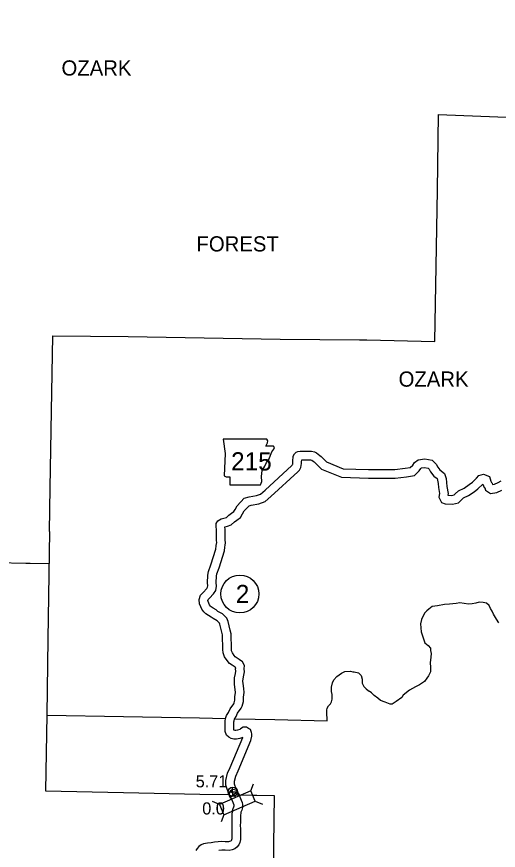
# Model space of a CAD drawing. Extents: x -939622 to -934245, y 1383184 to 1385301.
# Drawn here: x -936291.7 to -936241.4, y 1384683.1 to 1384770.1 of the extents above; entities that cross this region are included whole.
import ezdxf

# ---------------------------------------------------------------- set-up
doc = ezdxf.new("R2010")
doc.units = 0
for name, color, linetype in [('Level 10', 7, 'Continuous'), ('Level 11', 7, 'Continuous'), ('Level 2', 7, 'Continuous'), ('Level 20', 7, 'Continuous'), ('Level 21', 7, 'Continuous'), ('Level 25', 7, 'Continuous'), ('Level 26', 7, 'Continuous'), ('Level 27', 7, 'Continuous'), ('Level 8', 7, 'Continuous')]:
    doc.layers.add(name, color=color, linetype=linetype)

msp = doc.modelspace()

# ---------------------------------------------------------------- linework, layer by layer
at = {"layer": 'Level 10'}
for points in [[(-936270.814, 1384716.503), (-936270.849, 1384716.935), (-936270.833, 1384717.202), (-936270.672, 1384717.473), (-936270.337, 1384717.707), (-936269.901, 1384717.788), (-936269.76, 1384717.84), (-936269.519, 1384718.06), (-936269.233, 1384718.284), (-936268.989, 1384718.458), (-936268.88, 1384718.651), (-936268.648, 1384719.064), (-936267.91, 1384719.851), (-936267.396, 1384720.004), (-936266.628, 1384720.119), (-936266.219, 1384720.278), (-936265.738, 1384720.688), (-936262.945, 1384723.262), (-936262.904, 1384723.3), (-936262.873, 1384723.367), (-936262.86, 1384723.412), (-936262.85, 1384723.536), (-936262.835, 1384723.69), (-936262.813, 1384724.23), (-936262.691, 1384724.481), (-936262.506, 1384724.634), (-936262.342, 1384724.703), (-936262.094, 1384724.758), (-936260.892, 1384724.753), (-936260.598, 1384724.68), (-936260.398, 1384724.582), (-936260.198, 1384724.443), (-936260.043, 1384724.316), (-936259.906, 1384724.188), (-936259.344, 1384723.643), (-936257.591, 1384722.921), (-936254.949, 1384722.845)], [(-936269.917, 1384716.577), (-936269.94, 1384716.865), (-936269.66, 1384716.917), (-936269.283, 1384717.057), (-936268.937, 1384717.373), (-936268.695, 1384717.563), (-936268.304, 1384717.841), (-936268.096, 1384718.21), (-936267.917, 1384718.528), (-936267.42, 1384719.058), (-936267.2, 1384719.123), (-936266.396, 1384719.244), (-936265.751, 1384719.494), (-936265.141, 1384720.015), (-936262.331, 1384722.603), (-936262.159, 1384722.765), (-936262.027, 1384723.054), (-936261.97, 1384723.251), (-936261.954, 1384723.456), (-936261.937, 1384723.627), (-936261.928, 1384723.857), (-936261.004, 1384723.853), (-936260.907, 1384723.829), (-936260.855, 1384723.803), (-936260.741, 1384723.724), (-936260.636, 1384723.638), (-936260.526, 1384723.536), (-936259.846, 1384722.877), (-936257.781, 1384722.026), (-936254.974, 1384721.945)], [(-936254.957, 1384722.845), (-936252.885, 1384722.826), (-936252.221, 1384722.838), (-936251.132, 1384722.963), (-936250.598, 1384723.052), (-936250.34, 1384723.305), (-936250.151, 1384723.564), (-936249.771, 1384723.862), (-936249.099, 1384723.943), (-936248.304, 1384723.814), (-936247.899, 1384723.387), (-936247.743, 1384723.085), (-936247.51, 1384722.792), (-936247.033, 1384722.434), (-936246.87, 1384721.918), (-936246.812, 1384721.484), (-936246.773, 1384721.071), (-936246.654, 1384720.348), (-936246.682, 1384720.145), (-936246.279, 1384720.132), (-936246.022, 1384720.185), (-936245.92, 1384720.296), (-936245.563, 1384720.621), (-936244.993, 1384720.907), (-936244.467, 1384721.259), (-936244.126, 1384721.515), (-936243.684, 1384721.935), (-936243.447, 1384722.203), (-936242.948, 1384722.356), (-936242.334, 1384722.096), (-936242.196, 1384721.611), (-936242.138, 1384721.489), (-936242.062, 1384721.407), (-936242.014, 1384721.28), (-936241.826, 1384721.309), (-936241.44, 1384721.491), (-936241.133, 1384721.65)], [(-936254.966, 1384721.945), (-936252.881, 1384721.926), (-936252.161, 1384721.939), (-936251.007, 1384722.072), (-936250.171, 1384722.211), (-936249.657, 1384722.714), (-936249.498, 1384722.933), (-936249.414, 1384722.999), (-936249.117, 1384723.034), (-936248.748, 1384722.974), (-936248.64, 1384722.86), (-936248.502, 1384722.594), (-936248.142, 1384722.142), (-936247.805, 1384721.888), (-936247.752, 1384721.722), (-936247.707, 1384721.382), (-936247.666, 1384720.955), (-936247.564, 1384720.336), (-936247.615, 1384719.965), (-936247.348, 1384719.394), (-936246.958, 1384719.254), (-936246.202, 1384719.229), (-936245.556, 1384719.363), (-936245.285, 1384719.657), (-936245.048, 1384719.872), (-936244.539, 1384720.128), (-936243.946, 1384720.524), (-936243.544, 1384720.827), (-936243.045, 1384721.3), (-936242.891, 1384720.978), (-936242.84, 1384720.922), (-936242.742, 1384720.667), (-936242.235, 1384720.336), (-936241.561, 1384720.439), (-936241.063, 1384720.674)], [(-936269.34, 1384688.638), (-936269.563, 1384689.151), (-936269.712, 1384689.481), (-936269.825, 1384689.888), (-936269.84, 1384690.406), (-936269.664, 1384691.148), (-936269.383, 1384691.753), (-936268.077, 1384694.871), (-936268.377, 1384694.787), (-936268.716, 1384694.699), (-936269.012, 1384694.721), (-936269.268, 1384694.782), (-936269.529, 1384694.913), (-936269.755, 1384695.129), (-936269.9, 1384695.501), (-936269.912, 1384695.79), (-936269.895, 1384695.933), (-936269.902, 1384696.167), (-936269.9, 1384696.346), (-936269.901, 1384696.585), (-936269.861, 1384696.845), (-936269.753, 1384697.165), (-936269.574, 1384697.483), (-936269.393, 1384697.868), (-936269.022, 1384698.391), (-936268.97, 1384698.496), (-936268.884, 1384698.757), (-936268.894, 1384699.109), (-936268.847, 1384699.581), (-936268.867, 1384699.893), (-936268.927, 1384700.412), (-936268.952, 1384700.745), (-936268.943, 1384701.115), (-936268.836, 1384701.543), (-936268.809, 1384701.782), (-936268.816, 1384702.038), (-936268.81, 1384702.162), (-936268.98, 1384702.282), (-936269.165, 1384702.423), (-936269.474, 1384702.609), (-936269.713, 1384702.906), (-936269.964, 1384703.304), (-936270.128, 1384703.726), (-936270.154, 1384704.051), (-936270.187, 1384705.573), (-936270.253, 1384705.879), (-936270.453, 1384706.709), (-936270.499, 1384706.823), (-936270.731, 1384707.051), (-936271.161, 1384707.281), (-936271.376, 1384707.449), (-936271.648, 1384707.623), (-936271.914, 1384707.796), (-936272.126, 1384707.993), (-936272.331, 1384708.281), (-936272.435, 1384708.523), (-936272.583, 1384708.839), (-936272.615, 1384709.259), (-936272.478, 1384709.714), (-936272.215, 1384710.018), (-936271.837, 1384710.416), (-936271.743, 1384710.56), (-936271.714, 1384710.715), (-936271.746, 1384711.032), (-936271.702, 1384711.814), (-936271.646, 1384712.187), (-936271.39, 1384712.881), (-936270.883, 1384714.516), (-936270.851, 1384714.885), (-936270.802, 1384715.103), (-936270.788, 1384715.204), (-936270.809, 1384715.463), (-936270.815, 1384716.537)], [(-936268.515, 1384688.997), (-936268.74, 1384689.515), (-936268.864, 1384689.789), (-936268.929, 1384690.022), (-936268.937, 1384690.313), (-936268.809, 1384690.851), (-936268.559, 1384691.39), (-936267.236, 1384694.548), (-936267.141, 1384695.008), (-936267.117, 1384695.264), (-936267.158, 1384695.409), (-936267.257, 1384695.708), (-936267.466, 1384695.83), (-936267.674, 1384695.956), (-936268.015, 1384695.954), (-936268.307, 1384695.787), (-936268.384, 1384695.719), (-936268.611, 1384695.656), (-936268.798, 1384695.608), (-936268.874, 1384695.613), (-936268.958, 1384695.633), (-936268.992, 1384695.65), (-936269.007, 1384695.689), (-936269.01, 1384695.754), (-936268.993, 1384695.892), (-936269.001, 1384696.175), (-936269, 1384696.344), (-936269.001, 1384696.518), (-936268.983, 1384696.631), (-936268.927, 1384696.798), (-936268.774, 1384697.07), (-936268.613, 1384697.413), (-936268.248, 1384697.927), (-936268.135, 1384698.153), (-936267.98, 1384698.626), (-936267.993, 1384699.077), (-936267.944, 1384699.565), (-936267.97, 1384699.973), (-936268.031, 1384700.497), (-936268.051, 1384700.769), (-936268.046, 1384700.993), (-936267.949, 1384701.382), (-936267.908, 1384701.744), (-936267.916, 1384702.027), (-936267.896, 1384702.382), (-936268.108, 1384702.769), (-936268.448, 1384703.008), (-936268.659, 1384703.169), (-936268.873, 1384703.297), (-936268.978, 1384703.429), (-936269.156, 1384703.711), (-936269.241, 1384703.929), (-936269.255, 1384704.096), (-936269.289, 1384705.68), (-936269.376, 1384706.08), (-936269.594, 1384706.987), (-936269.736, 1384707.334), (-936270.191, 1384707.783), (-936270.668, 1384708.038), (-936270.856, 1384708.185), (-936271.16, 1384708.379), (-936271.357, 1384708.508), (-936271.446, 1384708.59), (-936271.543, 1384708.726), (-936271.614, 1384708.891), (-936271.698, 1384709.071), (-936271.705, 1384709.16), (-936271.671, 1384709.271), (-936271.548, 1384709.413), (-936271.129, 1384709.855), (-936270.892, 1384710.217), (-936270.805, 1384710.675), (-936270.843, 1384711.053), (-936270.806, 1384711.722), (-936270.77, 1384711.962), (-936270.538, 1384712.592), (-936269.995, 1384714.341), (-936269.96, 1384714.747), (-936269.916, 1384714.943), (-936269.884, 1384715.178), (-936269.909, 1384715.501), (-936269.915, 1384716.543)], [(-936268.68, 1384689.342), (-936268.519, 1384689.006), (-936268.462, 1384688.879)]]:
    msp.add_lwpolyline(points, dxfattribs=at)
at = {"layer": 'Level 11'}
for points in [[(-936268.68, 1384689.342), (-936268.519, 1384689.006), (-936268.37, 1384688.671), (-936268.225, 1384688.339), (-936268.144, 1384688.107), (-936268.095, 1384687.87), (-936268.1, 1384687.581), (-936268.178, 1384687.297), (-936268.266, 1384687.099), (-936268.289, 1384687.034), (-936268.306, 1384686.741), (-936268.315, 1384686.386), (-936268.321, 1384686.058), (-936268.327, 1384685.712), (-936268.321, 1384685.364), (-936268.318, 1384684.998), (-936268.312, 1384684.632), (-936268.319, 1384684.248), (-936268.365, 1384683.933), (-936268.487, 1384683.665), (-936268.682, 1384683.438), (-936268.916, 1384683.266), (-936269.189, 1384683.15), (-936269.505, 1384683.097), (-936269.918, 1384683.107), (-936270.254, 1384683.118), (-936270.562, 1384683.094)], [(-936269.491, 1384688.954), (-936269.336, 1384688.629), (-936269.193, 1384688.309), (-936269.064, 1384688.01), (-936269.013, 1384687.866), (-936268.997, 1384687.786), (-936268.998, 1384687.709), (-936269.028, 1384687.601), (-936269.101, 1384687.436), (-936269.18, 1384687.217), (-936269.205, 1384686.778), (-936269.215, 1384686.406), (-936269.221, 1384686.074), (-936269.227, 1384685.712), (-936269.221, 1384685.352), (-936269.218, 1384684.986), (-936269.212, 1384684.632), (-936269.218, 1384684.32), (-936269.237, 1384684.19), (-936269.253, 1384684.155), (-936269.298, 1384684.103), (-936269.365, 1384684.053), (-936269.443, 1384684.02), (-936269.569, 1384683.999), (-936269.892, 1384684.006), (-936270.274, 1384684.019), (-936270.653, 1384683.989), (-936271.024, 1384683.943), (-936271.356, 1384683.902), (-936271.742, 1384683.864), (-936272.185, 1384683.776), (-936272.418, 1384683.666), (-936272.649, 1384683.509), (-936272.829, 1384683.303), (-936272.969, 1384683.075)]]:
    msp.add_lwpolyline(points, dxfattribs=at)
at = {"layer": 'Level 2'}
for points in [[(-936255.136, 1384736.381), (-936248.036, 1384736.189), (-936247.889, 1384744.061), (-936247.757, 1384751.98), (-936247.652, 1384759.881), (-936239.705, 1384759.57), (-936239.604, 1384767.528), (-936239.509, 1384775.26), (-936231.735, 1384775.112), (-936223.865, 1384774.959), (-936216.107, 1384774.837), (-936215.972, 1384782.762), (-936207.838, 1384782.718), (-936207.773, 1384785.45)], [(-936255.136, 1384736.381), (-936248.036, 1384736.189), (-936247.889, 1384744.061), (-936247.757, 1384751.98), (-936247.652, 1384759.881), (-936239.705, 1384759.57), (-936239.604, 1384767.528), (-936239.509, 1384775.26), (-936231.735, 1384775.112), (-936223.865, 1384774.959), (-936216.107, 1384774.837), (-936215.972, 1384782.762), (-936207.838, 1384782.718), (-936207.773, 1384785.45)], [(-936288.235, 1384716.364), (-936288.172, 1384720.935), (-936288.036, 1384728.922), (-936287.89, 1384736.781), (-936280.017, 1384736.702), (-936272.099, 1384736.564), (-936264.189, 1384736.432), (-936255.904, 1384736.382), (-936255.136, 1384736.381)], [(-936288.235, 1384716.364), (-936288.172, 1384720.935), (-936288.036, 1384728.922), (-936287.89, 1384736.781), (-936280.017, 1384736.702), (-936272.099, 1384736.564), (-936264.189, 1384736.432), (-936255.904, 1384736.382), (-936255.136, 1384736.381)], [(-936288.235, 1384716.364), (-936288.398, 1384705.128), (-936288.512, 1384697.23), (-936288.653, 1384689.325), (-936280.508, 1384689.147), (-936272.567, 1384688.98), (-936269.576, 1384688.92)], [(-936288.235, 1384716.364), (-936288.398, 1384705.128), (-936288.512, 1384697.23), (-936288.653, 1384689.325), (-936280.508, 1384689.147), (-936272.567, 1384688.98), (-936269.537, 1384688.92)], [(-936268.413, 1384688.897), (-936264.806, 1384688.825), (-936264.912, 1384680.993)], [(-936266.971, 1384688.869), (-936264.806, 1384688.825), (-936264.912, 1384680.993)]]:
    msp.add_lwpolyline(points, dxfattribs=at)
at = {"layer": 'Level 20'}
for p, q in [((-936267.239, 1384689.32), (-936266.947, 1384690.056)), ((-936270.508, 1384687.902), (-936271.245, 1384688.193)), ((-936266.766, 1384688.23), (-936266.029, 1384687.939)), ((-936270.036, 1384686.812), (-936270.327, 1384686.076))]:
    msp.add_line(p, q, dxfattribs=at)
msp.add_lwpolyline([(-936270.036, 1384686.812), (-936266.766, 1384688.23), (-936267.239, 1384689.32), (-936270.508, 1384687.902)], close=True, dxfattribs=at)
at = {"layer": 'Level 21'}
msp.add_lwpolyline([(-936270.132, 1384726.022), (-936269.904, 1384724.499), (-936270.006, 1384722.19), (-936269.803, 1384722.063), (-936269.422, 1384722.063), (-936269.422, 1384721.251), (-936266.224, 1384721.251), (-936266.072, 1384721.581), (-936266.123, 1384722.114), (-936266.047, 1384722.723), (-936265.768, 1384723.205), (-936265.59, 1384723.56), (-936265.336, 1384723.941), (-936265.184, 1384724.347), (-936265.057, 1384724.677), (-936264.829, 1384724.956), (-936264.778, 1384725.134), (-936264.879, 1384725.261), (-936265.666, 1384725.261), (-936265.489, 1384725.616), (-936265.463, 1384725.844), (-936265.568, 1384726.02)], close=True, dxfattribs=at)
at = {"layer": 'Level 26'}
for p, q in [((-936269.607, 1384689.198), (-936268.631, 1384689.22)), ((-936269.389, 1384688.637), (-936268.636, 1384689.259)), ((-936268.782, 1384688.668), (-936269.324, 1384689.324)), ((-936269.108, 1384688.721), (-936269.13, 1384689.697))]:
    msp.add_line(p, q, dxfattribs=at)
msp.add_circle((-936269.119, 1384689.209), 0.488, dxfattribs=at)
msp.add_arc((-936269.013, 1384688.948), 0.488, 340.26675, 242.44563, dxfattribs=at)
at = {"layer": 'Level 27'}
msp.add_circle((-936268.376, 1384709.851), 1.98, dxfattribs=at)
at = {"layer": 'Level 8'}
for points in [[(-936310.654, 1384713.404), (-936304.177, 1384713.293), (-936296.207, 1384713.175), (-936288.283, 1384713.03)], [(-936290.692, 1384713.074), (-936288.283, 1384713.03)], [(-936241.364, 1384706.843), (-936241.605, 1384707.208), (-936241.934, 1384707.741), (-936242.051, 1384708.054), (-936242.225, 1384708.33), (-936242.376, 1384708.657), (-936242.65, 1384708.879), (-936242.981, 1384708.956), (-936243.405, 1384709.013), (-936243.749, 1384708.877), (-936244.146, 1384708.829), (-936244.544, 1384708.806), (-936245.433, 1384708.916), (-936245.831, 1384708.866), (-936246.503, 1384708.779), (-936247.044, 1384708.738), (-936247.751, 1384708.617), (-936248.304, 1384708.539), (-936248.682, 1384708.279), (-936248.881, 1384708.101), (-936249.116, 1384707.858), (-936249.443, 1384707.194), (-936249.523, 1384706.732), (-936249.476, 1384705.907), (-936249.341, 1384705.487), (-936249.086, 1384704.741), (-936248.736, 1384704.478), (-936248.505, 1384704.198), (-936248.497, 1384703.952), (-936248.428, 1384703.635), (-936248.452, 1384703.244), (-936248.542, 1384702.674), (-936248.497, 1384702.216), (-936248.504, 1384701.723), (-936248.684, 1384701.323), (-936248.865, 1384701.072), (-936249.109, 1384700.737), (-936249.626, 1384700.371), (-936250.064, 1384700.152), (-936250.671, 1384699.805), (-936251.355, 1384699.31), (-936251.467, 1384699.065), (-936252.075, 1384698.625), (-936252.5, 1384698.349), (-936252.707, 1384698.371), (-936253.209, 1384698.556), (-936253.719, 1384698.743), (-936253.984, 1384698.975), (-936254.38, 1384699.276), (-936254.64, 1384699.543), (-936254.874, 1384699.695)], [(-936268.836, 1384696.839), (-936264.734, 1384696.743), (-936259.284, 1384696.634), (-936259.285, 1384696.781), (-936259.275, 1384696.964), (-936259.297, 1384697.222), (-936259.302, 1384697.483), (-936259.294, 1384697.747), (-936259.283, 1384697.921), (-936259.123, 1384698.174), (-936258.933, 1384698.391), (-936258.818, 1384698.59), (-936258.742, 1384698.879), (-936258.754, 1384699.358), (-936258.822, 1384699.661), (-936258.819, 1384700.143), (-936258.726, 1384700.597), (-936258.587, 1384700.889), (-936258.257, 1384701.248), (-936257.768, 1384701.588), (-936257.416, 1384701.749), (-936256.833, 1384701.811), (-936256.599, 1384701.738)], [(-936256.599, 1384701.738), (-936256.459, 1384701.712), (-936256.015, 1384701.613), (-936255.732, 1384701.333), (-936255.631, 1384700.977), (-936255.617, 1384700.554), (-936255.453, 1384700.19), (-936255.212, 1384699.943), (-936255.004, 1384699.782), (-936254.874, 1384699.695)], [(-936288.472, 1384697.197), (-936280.501, 1384697.065), (-936272.598, 1384696.927), (-936269.883, 1384696.863)]]:
    msp.add_lwpolyline(points, dxfattribs=at)

# ---------------------------------------------------------------- texts
at = {"layer": 'Level 21'}
msp.add_text('215', height=1.9008, dxfattribs=at).set_placement((-936269.29, 1384722.738))
at = {"layer": 'Level 25'}
for s, p in [('5.71', (-936272.98, 1384689.676)), ('0.0', (-936272.299, 1384686.845))]:
    msp.add_text(s, height=1.2672, dxfattribs=at).set_placement(p)
at = {"layer": 'Level 27'}
msp.add_text('2', height=1.901, dxfattribs=at).set_placement((-936268.801, 1384708.901))
at = {"layer": 'Level 8'}
for s, p in [('OZARK', (-936286.983, 1384763.944)), ('FOREST', (-936272.901, 1384745.589)), ('OZARK', (-936251.819, 1384731.483))]:
    msp.add_text(s, height=1.584, dxfattribs=at).set_placement(p)

doc.saveas('drawing.dxf')
